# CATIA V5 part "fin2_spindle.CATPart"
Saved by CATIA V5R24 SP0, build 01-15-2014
Part number: Spindle
Bounding box of the stored display mesh (mm): x -15 to 15, y -3.164 to 3.164, z -50 to 0
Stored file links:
  G:\내 드라이브\04_WORK\00_LECTURE\CAD2020\exam\fin2_spindle.CATPart
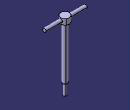
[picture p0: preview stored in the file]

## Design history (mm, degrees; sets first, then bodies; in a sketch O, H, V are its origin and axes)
Body1 (main body)
  Sketch1 on yz-plane, origin (0, 0, 0), H (0, 1, 0), V (0, 0, 1)
    axis line L1 (0, 0) -> (0, -9.8621)
    line L2 (0, 0) -> (-3.2, 0)
    line L3 (-3.2, 0) -> (-3.2, -4)
    line L4 (-3.2, -4) -> (-1.75, -4)
    line L5 (-1.75, -4) -> (-1.75, -42)
    line L6 (-1.75, -42) -> (-1.25, -42)
    line L7 (-1.25, -42) -> (-1.25, -50)
    line L8 (-1.25, -50) -> (0, -50)
    point P8 (0, -50)
    line L9 (0, -50) -> (0, 0)
    length L3 = 4
    distance L8 H = 50
    distance L6 H = 42
    distance L3 V = 3.2
    distance L5 L9 = 1.75
    distance L7 L9 = 1.25
    vertical: L1 V, L3 V, L5 V, L7 V, L9 V
    horizontal: L2 H, L4 H, L6 H, L8 H
    coincidence: P8 L1
  Shaft1: profile Sketch1, axis Sketch1.L1, angle 360
  Sketch2 on yz-plane, origin (0, 0, 0), H (0, 1, 0), V (0, 0, 1)
    reference projected line E1 through (0, 0) direction (0, -1) from axis of face of Shaft1 from Sketch1.L5
    circle A1 centre (0, -2) radius 1.25
    point P5 (0, -2)
    radius A1 = 1.25
    distance P5 H = 2
    coincidence: P5 E1
  Pad1: profile Sketch2, direction (1, 0, 0), length 15, mirrored extent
